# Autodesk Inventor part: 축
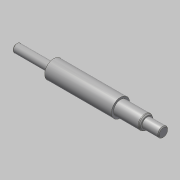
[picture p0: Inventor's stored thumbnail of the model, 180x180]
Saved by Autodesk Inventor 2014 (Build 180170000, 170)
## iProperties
Created: 2016-05
Part Number: 축
Document SubType Name: Modeling
Designer: mduedu
Density: 7.86 g/cm^3
Material: 강철, 연강
Appearance: 강철
Author: mduedu
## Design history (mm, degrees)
sketch "스케치1"
  geometry: L1 (-44, 11)-(-44, 5); L2 (37, 11)-(37, 8.5); L3 (-89, 0)-(89, 0); L4 (-44, 11)-(37, 11); L5 (37, 11)-(37, 8.5); L6 (-44, 11)-(-44, 5); L7 (-44, 5)-(-89, 5); L8 (-89, 5)-(-89, 0); L9 (37, 8.5)-(69, 8.5); L10 (89, 6)-(89, 0); L11 (69, 8.5)-(69, 6); L12 (69, 6)-(89, 6); 1 further point
  constraints: 24 end point, 9 perpendicular, 2 midpoint, 1 horizontal
  dimensions: "d0" = 22 diameter of L4 L3; "d1" = 10 diameter of L7 L3; "d2" = 45 distance between parallel lines of L8 L1; "d3" = 52 distance between parallel lines of L10 L2; "d4" = 12 diameter of L12 L3; "d5" = 20 distance between parallel lines of L10 L11; "d29" = 81 distance of L1.start L2.start; "d37" = 17 diameter of L9 L3
revolve "회전1" stored, may be unused: angle "d6" = 90 deg
chamfer "모따기2" distance "d32" = 1; stored, may be unused: second distance "d33" = 2, angle "d34" = 45 deg
node "작업 평면4"
sketch "스케치4"
  geometry: L1 (-5, 2)-(5, 2); L2 (5, -2)-(-5, -2); L3 (-10, -5)-(-10, 5) reference; A1 r 2 centre (5, 0) between (5, -2) and (5, 2); A2 r 2 centre (-5, 0) between (-5, 2) and (-5, -2); 1 further point
  constraints: 4 end point, 4 point on circle, 4 tangent, 2 centre point, 1 horizontal, 1 horizontal alignment, 1 parallel
  dimensions: "d20" = 4 distance between parallel lines of L2 L1; "d21" = 14 dimension on A1 A2; "d35" = 3 distance edge to line of A2 L3
extrude "돌출3" cut sketch "스케치4" distance "d23" = 2.5; taper "d24" = 0 deg
node "작업 평면5"
sketch "스케치5"
  geometry: L1 (22.5, 1.5)-(12, 1.5); L2 (12, -1.5)-(22.5, -1.5); L3 (22.5, 4)-(22.5, -4) reference; A1 r 1.5 centre (12, 0) between (12, 1.5) and (12, -1.5); 3 further points
  constraints: 4 end point, 2 horizontal alignment, 2 point on circle, 2 point on line, 2 tangent, 1 centre point, 1 coincident, 1 horizontal, 1 midpoint
  dimensions: "d25" = 3 distance between parallel lines of L2 L1; "d36" = 12 dimension on A1 L3
extrude "돌출4" cut sketch "스케치5" distance "d27" = 1.8; taper "d28" = 0 deg
chamfer "모따기3" distance "d38" = 1.82; stored, may be unused: second distance "d39" = 2, angle "d40" = 30 deg
fillet "모깎기1" dims "d41" = 2
node "솔리드1"
